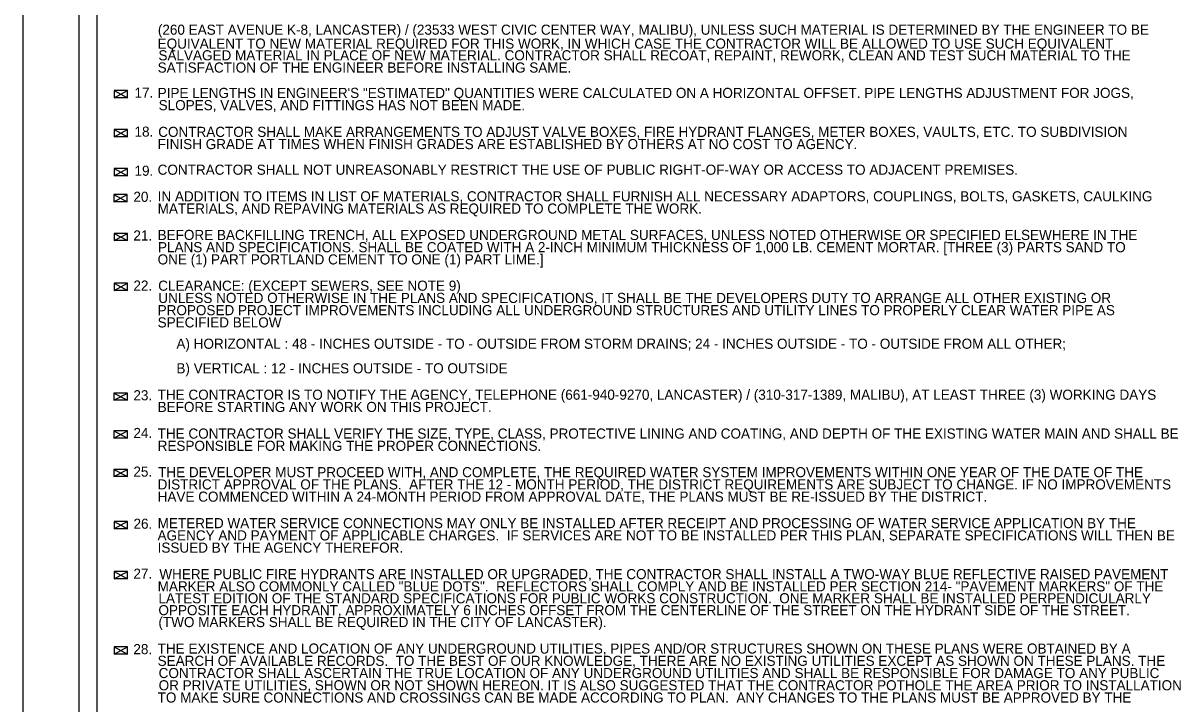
# Model space of a CAD drawing. Extents: x 837 to 1117, y 1316 to 1424.
# Drawn here: x 843.02 to 853.33, y 1404.23 to 1410.3 of the extents above; entities that cross this region are included whole.
import ezdxf

# ---------------------------------------------------------------- set-up
doc = ezdxf.new("R2010")
doc.units = 0
for name, color, linetype in [('BASEMAP', 7, 'Continuous'), ('LLINES', 7, 'Continuous'), ('TEXT', 7, 'Continuous')]:
    doc.layers.add(name, color=color, linetype=linetype)

msp = doc.modelspace()

# ---------------------------------------------------------------- linework, layer by layer
at = {"layer": 'BASEMAP'}
for p, q in [((843.02, 1399.24), (843.02, 1421.24)), ((843.52, 1399.74), (843.52, 1420.74)), ((843.678, 1399.867), (843.678, 1420.065))]:
    msp.add_line(p, q, dxfattribs=at)
at = {"layer": 'LLINES'}
for p, q in [((843.83, 1409.633), (843.949, 1409.697)), ((843.83, 1409.697), (843.83, 1409.633)), ((843.83, 1409.697), (843.949, 1409.633)), ((843.949, 1409.697), (843.83, 1409.697)), ((843.949, 1409.633), (843.949, 1409.697)), ((843.949, 1409.633), (843.83, 1409.633)), ((843.949, 1409.351), (843.83, 1409.351)), ((843.83, 1409.351), (843.949, 1409.286)), ((843.83, 1409.351), (843.83, 1409.286)), ((843.83, 1409.286), (843.949, 1409.351)), ((843.949, 1409.286), (843.949, 1409.351)), ((843.949, 1409.286), (843.83, 1409.286)), ((843.83, 1408.938), (843.949, 1409.003)), ((843.83, 1409.003), (843.83, 1408.938)), ((843.83, 1409.003), (843.949, 1408.938)), ((843.949, 1409.003), (843.83, 1409.003)), ((843.949, 1408.938), (843.83, 1408.938)), ((843.949, 1408.938), (843.949, 1409.003)), ((843.827, 1408.706), (843.946, 1408.77)), ((843.827, 1408.77), (843.827, 1408.706)), ((843.827, 1408.77), (843.946, 1408.706)), ((843.946, 1408.77), (843.827, 1408.77)), ((843.946, 1408.706), (843.946, 1408.77)), ((843.946, 1408.706), (843.827, 1408.706)), ((843.949, 1408.425), (843.83, 1408.425)), ((843.83, 1408.425), (843.949, 1408.361)), ((843.83, 1408.425), (843.83, 1408.361)), ((843.83, 1408.361), (843.949, 1408.425)), ((843.949, 1408.361), (843.949, 1408.425)), ((843.949, 1408.361), (843.83, 1408.361)), ((843.83, 1407.915), (843.949, 1407.98)), ((843.83, 1407.98), (843.83, 1407.915)), ((843.83, 1407.98), (843.949, 1407.915)), ((843.949, 1407.98), (843.83, 1407.98)), ((843.949, 1407.915), (843.83, 1407.915)), ((843.949, 1407.915), (843.949, 1407.98)), ((843.949, 1407.002), (843.829, 1407.002)), ((843.829, 1407.002), (843.949, 1406.938)), ((843.829, 1407.002), (843.829, 1406.938)), ((843.829, 1406.938), (843.949, 1407.002)), ((843.949, 1406.938), (843.949, 1407.002)), ((843.949, 1406.938), (843.829, 1406.938)), ((843.829, 1406.602), (843.949, 1406.667)), ((843.829, 1406.667), (843.829, 1406.602)), ((843.829, 1406.667), (843.949, 1406.602)), ((843.949, 1406.667), (843.829, 1406.667)), ((843.949, 1406.602), (843.949, 1406.667)), ((843.949, 1406.602), (843.829, 1406.602)), ((843.949, 1406.323), (843.829, 1406.323)), ((843.829, 1406.323), (843.949, 1406.258)), ((843.829, 1406.323), (843.829, 1406.258)), ((843.829, 1406.258), (843.949, 1406.323)), ((843.949, 1406.258), (843.829, 1406.258)), ((843.949, 1406.258), (843.949, 1406.323)), ((843.83, 1405.859), (843.83, 1405.794)), ((843.95, 1405.859), (843.83, 1405.859)), ((843.95, 1405.794), (843.95, 1405.859)), ((843.95, 1405.794), (843.83, 1405.794)), ((843.83, 1405.414), (843.95, 1405.349)), ((843.83, 1405.349), (843.95, 1405.414)), ((843.83, 1405.414), (843.83, 1405.349)), ((843.95, 1405.414), (843.83, 1405.414)), ((843.95, 1405.349), (843.95, 1405.414)), ((843.95, 1405.349), (843.83, 1405.349)), ((843.83, 1404.741), (843.95, 1404.676)), ((843.83, 1404.676), (843.95, 1404.741)), ((843.83, 1404.741), (843.83, 1404.676)), ((843.95, 1404.741), (843.83, 1404.741)), ((843.95, 1404.676), (843.95, 1404.741)), ((843.95, 1404.676), (843.83, 1404.676))]:
    msp.add_line(p, q, dxfattribs=at)
at = {"layer": 'TEXT'}
for p, q in [((843.95, 1405.859), (843.83, 1405.794)), ((843.83, 1405.859), (843.95, 1405.794))]:
    msp.add_line(p, q, dxfattribs=at)

# ---------------------------------------------------------------- texts
at = {"layer": 'LLINES'}
for s, p in [('(260 EAST AVENUE K-8, LANCASTER) / (23533 WEST CIVIC CENTER WAY, MALIBU), UNLESS SUCH MATERIAL IS DETERMINED BY THE ENGINEER TO BE', (844.22, 1410.194)), ('EQUIVALENT TO NEW MATERIAL REQUIRED FOR THIS WORK, IN WHICH CASE THE CONTRACTOR WILL BE ALLOWED TO USE SUCH EQUIVALENT', (844.218, 1410.07)), ('SALVAGED MATERIAL IN PLACE OF NEW MATERIAL. CONTRACTOR SHALL RECOAT, REPAINT, REWORK, CLEAN AND TEST SUCH MATERIAL TO THE', (844.225, 1409.966)), ('SATISFACTION OF THE ENGINEER BEFORE INSTALLING SAME.', (844.218, 1409.857)), ('17.', (844.012, 1409.633)), ('PIPE LENGTHS IN ENGINEER\'S "ESTIMATED" QUANTITIES WERE CALCULATED ON A HORIZONTAL OFFSET. PIPE LENGTHS ADJUSTMENT FOR JOGS,', (844.218, 1409.631)), ('SLOPES, VALVES, AND FITTINGS HAS NOT BEEN MADE.', (844.227, 1409.522)), ('18.', (844.012, 1409.286)), ('CONTRACTOR SHALL MAKE ARRANGEMENTS TO ADJUST VALVE BOXES, FIRE HYDRANT FLANGES, METER BOXES, VAULTS, ETC. TO SUBDIVISION', (844.223, 1409.284)), ('FINISH GRADE AT TIMES WHEN FINISH GRADES ARE ESTABLISHED BY OTHERS AT NO COST TO AGENCY.', (844.218, 1409.175)), ('19.', (844.012, 1408.938)), ('CONTRACTOR SHALL NOT UNREASONABLY RESTRICT THE USE OF PUBLIC RIGHT-OF-WAY OR ACCESS TO ADJACENT PREMISES.', (844.218, 1408.947)), ('20.', (844.002, 1408.706)), ('IN ADDITION TO ITEMS IN LIST OF MATERIALS, CONTRACTOR SHALL FURNISH ALL NECESSARY ADAPTORS, COUPLINGS, BOLTS, GASKETS, CAULKING', (844.218, 1408.71)), ('MATERIALS, AND REPAVING MATERIALS AS REQUIRED TO COMPLETE THE WORK.', (844.218, 1408.601)), ('21.', (844.002, 1408.361)), ('BEFORE BACKFILLING TRENCH, ALL EXPOSED UNDERGROUND METAL SURFACES, UNLESS NOTED OTHERWISE OR SPECIFIED ELSEWHERE IN THE', (844.218, 1408.366)), ('PLANS AND SPECIFICATIONS. SHALL BE COATED WITH A 2-INCH MINIMUM THICKNESS OF 1,000 LB. CEMENT MORTAR. [THREE (3) PARTS SAND TO', (844.221, 1408.257)), ('ONE (1) PART PORTLAND CEMENT TO ONE (1) PART LIME.]', (844.218, 1408.148)), ('22.', (844.002, 1407.915)), ('CLEARANCE: (EXCEPT SEWERS, SEE NOTE 9)', (844.223, 1407.914)), ('UNLESS NOTED OTHERWISE IN THE PLANS AND SPECIFICATIONS, IT SHALL BE THE DEVELOPERS DUTY TO ARRANGE ALL OTHER EXISTING OR', (844.224, 1407.805)), ('PROPOSED PROJECT IMPROVEMENTS INCLUDING ALL UNDERGROUND STRUCTURES AND UTILITY LINES TO PROPERLY CLEAR WATER PIPE AS', (844.218, 1407.696)), ('SPECIFIED BELOW', (844.218, 1407.587)), ('     A) HORIZONTAL : 48 - INCHES OUTSIDE - TO - OUTSIDE FROM STORM DRAINS; 24 - INCHES OUTSIDE - TO - OUTSIDE FROM ALL OTHER;', (844.218, 1407.397)), ('     B) VERTICAL : 12 - INCHES OUTSIDE - TO OUTSIDE', (844.218, 1407.178)), ('23.', (844.002, 1406.938)), ('THE CONTRACTOR IS TO NOTIFY THE AGENCY, TELEPHONE (661-940-9270, LANCASTER) / (310-317-1389, MALIBU), AT LEAST THREE (3) WORKING DAYS', (844.218, 1406.943)), ('BEFORE STARTING ANY WORK ON THIS PROJECT.', (844.218, 1406.834)), ('24.', (844.002, 1406.602)), ('THE CONTRACTOR SHALL VERIFY THE SIZE, TYPE, CLASS, PROTECTIVE LINING AND COATING, AND DEPTH OF THE EXISTING WATER MAIN AND SHALL BE', (844.218, 1406.597)), ('RESPONSIBLE FOR MAKING THE PROPER CONNECTIONS.', (844.218, 1406.488)), ('25.', (844.002, 1406.258)), ('THE DEVELOPER MUST PROCEED WITH, AND COMPLETE, THE REQUIRED WATER SYSTEM IMPROVEMENTS WITHIN ONE YEAR OF THE DATE OF THE', (844.222, 1406.253)), ('DISTRICT APPROVAL OF THE PLANS.  AFTER THE 12 - MONTH PERIOD, THE DISTRICT REQUIREMENTS ARE SUBJECT TO CHANGE. IF NO IMPROVEMENTS', (844.218, 1406.144)), ('HAVE COMMENCED WITHIN A 24-MONTH PERIOD FROM APPROVAL DATE, THE PLANS MUST BE RE-ISSUED BY THE DISTRICT.', (844.218, 1406.035)), ('26.', (844.003, 1405.794)), ('METERED WATER SERVICE CONNECTIONS MAY ONLY BE INSTALLED AFTER RECEIPT AND PROCESSING OF WATER SERVICE APPLICATION BY THE', (844.218, 1405.799)), ('AGENCY AND PAYMENT OF APPLICABLE CHARGES.  IF SERVICES ARE NOT TO BE INSTALLED PER THIS PLAN, SEPARATE SPECIFICATIONS WILL THEN BE', (844.217, 1405.69)), ('ISSUED BY THE AGENCY THEREFOR.', (844.218, 1405.581)), ('27.', (844.002, 1405.349)), ('WHERE PUBLIC FIRE HYDRANTS ARE INSTALLED OR UPGRADED, THE CONTRACTOR SHALL INSTALL A TWO-WAY BLUE REFLECTIVE RAISED PAVEMENT', (844.233, 1405.345)), ('MARKER ALSO COMMONLY CALLED "BLUE DOTS".  REFLECTORS SHALL COMPLY AND BE INSTALLED PER SECTION 214- "PAVEMENT MARKERS" OF THE', (844.218, 1405.236)), ('LATEST EDITION OF THE STANDARD SPECIFICATIONS FOR PUBLIC WORKS CONSTRUCTION.  ONE MARKER SHALL BE INSTALLED PERPENDICULARLY', (844.225, 1405.13)), ('OPPOSITE EACH HYDRANT, APPROXIMATELY 6 INCHES OFFSET FROM THE CENTERLINE OF THE STREET ON THE HYDRANT SIDE OF THE STREET.', (844.225, 1405.024)), ('(TWO MARKERS SHALL BE REQUIRED IN THE CITY OF LANCASTER).', (844.225, 1404.918)), ('28.', (844.002, 1404.677)), ('THE EXISTENCE AND LOCATION OF ANY UNDERGROUND UTILITIES, PIPES AND/OR STRUCTURES SHOWN ON THESE PLANS WERE OBTAINED BY A', (844.218, 1404.682)), ('SEARCH OF AVAILABLE RECORDS.  TO THE BEST OF OUR KNOWLEDGE, THERE ARE NO EXISTING UTILITIES EXCEPT AS SHOWN ON THESE PLANS. THE', (844.218, 1404.573)), ('CONTRACTOR SHALL ASCERTAIN THE TRUE LOCATION OF ANY UNDERGROUND UTILITIES AND SHALL BE RESPONSIBLE FOR DAMAGE TO ANY PUBLIC', (844.227, 1404.464)), ('OR PRIVATE UTILITIES, SHOWN OR NOT SHOWN HEREON. IT IS ALSO SUGGESTED THAT THE CONTRACTOR POTHOLE THE AREA PRIOR TO INSTALLATION', (844.227, 1404.355)), ('TO MAKE SURE CONNECTIONS AND CROSSINGS CAN BE MADE ACCORDING TO PLAN.  ANY CHANGES TO THE PLANS MUST BE APPROVED BY THE', (844.218, 1404.246))]:
    msp.add_text(s, height=0.09, dxfattribs=at).set_placement(p)

doc.saveas('drawing.dxf')
